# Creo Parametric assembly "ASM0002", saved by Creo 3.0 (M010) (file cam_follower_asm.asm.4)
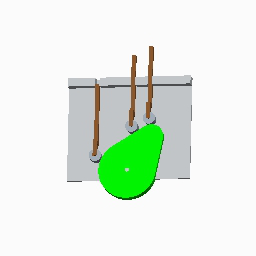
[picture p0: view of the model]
Units: Inch lbm Second (Pro/E Default); INCH, POUND, SECS

Created from: INLBS_ASM_DESIGN.ASM

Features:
  1. datum plane "ASM_RIGHT"
  2. datum plane "ASM_TOP"
  3. datum plane "ASM_FRONT"
  4. coordinate system
  5. component "BASE"
  6. component "CAM001"
  7. component "FOLLOWER_BAR"
  8. component "FOLLOWER_ROLLER"
  9. component "FOLLOWER_ASM", "ASM0001.ASM"
  10. component "FOLLOWER_ASM", "ASM0001.ASM"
